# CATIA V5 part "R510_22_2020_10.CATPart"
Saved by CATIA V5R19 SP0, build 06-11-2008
Material "Steel": density 7860 kg/m3, Young's modulus 2e+11 Pa, Poisson ratio 0.266, thermal expansion 1.17e-05 1/K
Bounding box of the stored display mesh (mm): x -9.942 to 9.969, y -9.942 to 9.942, z 0 to 82
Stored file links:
  G:\Podręcznik\CD\Narzędzia\Arkusz Excel\Modele narzędzi\R510.22-2020-10.CATPart
  C:\Program Files\Dassault Systemes\B19\intel_a\startup\materials\Catalog.CATMaterial
  F:\OSTATNIE\DesignTable2.xls
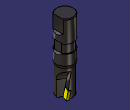
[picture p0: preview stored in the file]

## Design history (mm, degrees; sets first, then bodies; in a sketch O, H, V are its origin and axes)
Parameters
  CuttingType = "CUTTER"
  d = 20 mm {design table}
  D = 20 mm {design table}
  L = 82 mm {design table}
  l = 50 mm {design table}
  alfa = 11 deg {design table}
  gammap = 9 deg {design table}
  S = 3.18 mm {design table}
  epsilon = 85 deg {design table}
  lp = 10 mm {design table}
  x = 0.1131 mm {design table}
  gammaf = -12 deg {design table}
  z = 2 {design table}
  teta = 180 deg {design table}
  `lp'` = 9.8769 mm {design table}
  `lp''` = 5.8466 mm {design table}
Body1 "BODY" (main body), material "Steel"
  Sketch1 "sketch" on yz-plane, origin (0, 0, 0), H (0, 1, 0), V (0, 0, 1)
    line L1 (0, 1.3409) -> (9, 0.2358)
    line L2 (9, 0.2358) -> (9, 32)
    point P3 (9, 32)
    line L3 (9, 32) -> (9, 32)
    point P4 (10, 32)
    line L4 (10, 34.8284) -> (10, 47)
    point P5 (10, 47)
    line L5 (10, 47) -> (9, 47)
    line L6 (9, 47) -> (9, 57)
    line L7 (9, 57) -> (10, 57)
    point P8 (10, 57)
    line L8 (10, 57) -> (10, 81.2929)
    line L9 (10, 81.2929) -> (9.2929, 82)
    line L10 (9.2929, 82) -> (0, 82)
    point P11 (0, 82)
    line L11 (0, 82) -> (0, 1.3409)
    construction line L12 (0, -29.1199) -> (0, 199.3445)
    point P12 (0, -29.1199)
    construction line L13 (0, 0.1131) -> (10, 0.1131)
    point P14 (0, 0.1131)
    point P15 (10, 0.1131)
    construction line L14 (0, 1.3409) -> (10, 0.1131)
    axis line L15 (10, 0.1131) -> (10, -5.5625)
    line L16 (9, 32) -> (10, 34.8284)
    point P17 (9, 32)
    length L6 = 10 {= 0.2*l}
    distance P3 H = 32 {= L-l}
    length L9 = 1
    angle L8 L9 = 45
    distance L6 L8 = 1
    distance L8 L11 = 10 {= d/2}
    length L13 = 10 {= D/2}
    distance H L13 = 0.1131 {= x}
    distance L10 L7 = 25 {= 0.5*l}
    distance P15 L2 = 1
    distance P4 P5 = 15 {= 0.3*l}
    length L16 = 3 {= 0.2*(0.3*l)}
    angle L1 L2 = 83
    vertical: L2 V, L4 V, L6 V, L8 V, L11 V, L12 V, L15 V
    horizontal: L3 H, L5 H, L7 H, L10 H, L13 H
    coincidence: P8 L4, P11 V, P12 V, L1 L14, P14 L12, L3 P4, L4 P4, P3 P17
  Shaft1: profile Sketch1, axis Z axis, angle 360
  Fillet1: radius 1 {= 0.1*D/2}, on edge [face of Shaft1 from Sketch1.L1 | face of Shaft1 from Sketch1.L2]
  Sketch2 on zx-plane, origin (0, 0, 0), H (-1, 0, 0), V (0, 0, 1)
    line L1 (-8, 82) -> (-8, 67)
    line L2 (-8, 67) -> (-10, 65)
    line L3 (-10, 65) -> (-10, 59)
    line L4 (-10, 59) -> (-8, 57)
    point P5 (-8, 57)
    line L5 (-8, 57) -> (-8, 47)
    line L6 (-8, 47) -> (-10, 45)
    point P7 (-10, 45)
    line L7 (-10, 45) -> (-10, 45)
    line L8 (-10, 45) -> (-13, 45)
    line L9 (-13, 45) -> (-13, 82)
    line L10 (-13, 82) -> (-8, 82)
    reference projected line E1 through (0, 0) direction (0, 1) from axis of face of Shaft1 from Sketch1.L8
    reference projected line E2 (-9.2929, 82) -> (9.2929, 82) from edge [face of Shaft1 from Sketch1.L9 | face of Shaft1 from Sketch1.L10]
    distance L3 E1 = 10 {= d/2}
    distance L1 L3 = 2
    angle L2 L3 = 45
    angle L4 L3 = 45
    length L5 = 10 {= l*0.2}
    length L1 = 15 {= 0.3*l}
    distance P5 L10 = 25 {= 0.5*l}
    distance L9 L1 = 5
    distance L7 L5 = 2
    angle L5 L6 = 45
    vertical: L1 V, L3 V, L5 V, L7 V, L9 V
    horizontal: L8 H, L10 H
    coincidence: L10 E2, L1 L5, P7 L8
  Pocket1: profile Sketch2, direction (0, -1, 0), length 8, mirrored extent
  Plane1: type Angle, Angle 150, Direction Z axis, RefPlane yz-plane
  Plane2: type Offset, Offset 1, RefPlane Plane1, reversed
  Sketch3 "gammap_os_obrotu" on Plane2, origin (0.866, -0.5, 0), H (-0.5, -0.866, 0), V (0, 0, 1)
    line L1 (1.3076, 0) -> (-0.9434, 0)
    reference intersected line E1 through (0, 0) direction (-1, 0) from xy-plane
    horizontal: L1 H
    coincidence: E1 L1
  Plane3 "gammap": type Angle, Angle -9 {= -gammap}, Direction Sketch3, RefPlane Plane2
  Plane4: type Offset, Offset 0.5, RefPlane Plane3, reversed
  Sketch4 on Plane4, origin (1.2725, -0.7347, 0.2327), H (-0.5, -0.866, 0), V (-0.1355, 0.0782, 0.9877)
    line L1 (-10, -2.3223) -> (-10, 6.2448)
    distance V L1 = 10 {= D/2}
  Plane5 "gammaf": type Angle, Angle 12 {= -gammaf}, Direction Sketch4, RefPlane Plane4
  Plane6: type Offset, Offset 0.5, RefPlane Plane5
  Plane7: type Angle, Angle 90, Direction Sketch4, RefPlane Plane5
  Sketch5 on Plane7, origin (2.8716, 9.0198, -0.3577), H (0.9503, -0.3114, 0), V (0.0101, 0.0309, 0.9995)
    point P1 (3.6086, 0.3579)
    line L1 (3.6086, 0.3579) -> (0.3714, 0.4819)
    line L2 (0.3714, 0.4819) -> (-0.9703, 9.1423)
    line L3 (-0.9703, 9.1423) -> (2.0776, 10.24)
    line L4 (2.0776, 10.24) -> (3.6086, 0.3579)
    reference projected line E1 (3.9266, -1.6951) -> (2.6151, 6.7709) from Sketch4
    construction line L5 (2.0776, 10.24) -> (-2.825, 9.4805)
    axis line L6 (3.6086, 0.3579) -> (-0.0816, -0.2138)
    reference intersected line E2 through (-0.0001, 0.3579) direction (-1, 0) from xy-plane
    distance L2 L4 = 3.18 {= S}
    length L4 = 10 {= lp}
    angle L5 L3 = 11 {= alfa}
    angle L6 L1 = 11 {= alfa}
    coincidence: L4 E1, P1 E2
    perpendicularity: L5 L2
    parallelism: L6 L5
  Plane8: type Offset, Offset 10 {= D/2}, RefPlane Plane1, reversed
  Sketch6 on Plane8, origin (8.6603, -5, 0), H (-0.5, -0.866, 0), V (0, 0, 1)
    line L1 (-3.5247, -3) -> (-3.5247, 18.3474)
    arc A1 centre (-15.5247, 18.3474) radius 12 from (-3.5247, 18.3474) to (-10, 29) ccw
    point P4 (-10, 29)
    line L2 (-10, 29) -> (-10, -3)
    point P5 (-10, -3)
    line L3 (-10, -3) -> (-3.5247, -3)
    axis line L4 (-10, -3) -> (-3.5247, -2.4335)
    point P6 (-10, -3)
    point P7 (-3.5247, -2.4335)
    reference projected line E1 (-9, 32) -> (9, 32) from edge [face of Shaft1 from Sketch1.L2 | face of Shaft1 from Sketch1.L16]
    distance L2 V = 10 {= D/2}
    angle L4 L2 = 85 {= epsilon}
    distance E1 P4 = 3
    radius A1 = 12
    distance H L3 = 3
    length L4 = 6.5 {= 0.65*lp}
    vertical: L1 V, L2 V
    horizontal: L3 H
    tangency: L1 A1
    coincidence: P6 P5, P7 L1
  Pocket2: profile Sketch6, direction (-0.866, 0.5, 0), up to Plane6
  CircPattern1: of Pocket2, instances 2 {= z}, angular step 180 {= teta}, axis from Z axis
  Sketch7 on Plane5, origin (3.3239, -1.0481, 0.5894), H (-0.3066, -0.9518, 0), V (-0.1456, 0.0469, 0.9882)
    line L1 (-9.7669, 9.3981) -> (-3.8102, 10.1175)
    point P1 (-9.7669, 9.3981)
    reference projected point E1 (-9.7669, 9.3981) from vertex [element of Sketch5 | element of Sketch5]
    reference projected line E2 (-9.4279, -0.899) -> (-9.757, 9.0955) from Sketch5.L4
    length L1 = 6 {= 0.6*lp}
    angle E2 L1 = 85 {= epsilon}
    coincidence: P1 E1
  Slot1: profile Sketch5, centre curve Sketch7
  CircPattern2: of Slot1, instances 2 {= z}, angular step 180 {= teta}, axis from Z axis
Body2 "INSERTS"
  Sketch8 "CUT" on yz-plane, origin (0, 0, 0), H (0, 1, 0), V (0, 0, 1)
    line L1 (4.1757, 0.5096) -> (10, 0)
    point P2 (10, 0)
    line L2 (10, 0) -> (10, 9.8769)
    line L3 (10, 9.8769) -> (4.1757, 10.3864)
    line L4 (4.1757, 10.3864) -> (4.1757, 0.5096)
    angle L3 L4 = 85
    length L2 = 9.8769 {= `lp'`}
    length L1 = 5.8466 {= `lp''`}
    distance L2 V = 10 {= D/2}
    vertical: L2 V, L4 V
    parallelism: L3 L1
    coincidence: P2 H
  Sketch9 "NOCUT" on yz-plane, origin (0, 0, 0), H (0, 1, 0), V (0, 0, 1)
    axis line L1 (10, 0) -> (0, 0.8749)
    point P1 (0, 0.8749)
    point P2 (10, 0)
    reference projected line E1 (4.0228, 0.5229) -> (10, 0) from Sketch8.L1
    reference projected point E2 (10, 0) from vertex [element of Sketch8 | element of Sketch8]
    line L2 (0, 0.8749) -> (4.1757, 0.5096)
    point P3 (4.1757, 0.5096)
    line L3 (4.1757, 0.5096) -> (4.1757, 10.3864)
    line L4 (4.1757, 10.3864) -> (9, 9.9644)
    line L5 (9, 9.9644) -> (9, 32)
    line L6 (9, 32) -> (10, 32)
    line L7 (10, 32) -> (10, 47)
    line L8 (10, 47) -> (9, 47)
    line L9 (9, 47) -> (9, 57)
    line L10 (9, 57) -> (10, 57)
    point P11 (10, 57)
    line L11 (10, 57) -> (10, 81.2929)
    point P12 (10, 82)
    line L12 (9.2929, 82) -> (0, 82)
    point P13 (0, 82)
    line L13 (0, 82) -> (0, 0.8749)
    line L14 (10, 81.2929) -> (9.2929, 82)
    length L9 = 10 {= 0.2*l}
    length L7 = 15 {= 0.3*l}
    distance L6 H = 32 {= L-l}
    distance L11 L13 = 10 {= d/2}
    distance L9 L11 = 1
    distance P3 P2 = 5.8466 {= `lp''`}
    distance L9 L7 = 1
    distance L5 P2 = 1
    length L3 = 9.8769 {= `lp'`}
    angle L10 L9 = 90
    distance P11 P12 = 25 {= 0.5*l}
    angle L11 L14 = 45
    length L14 = 1
    coincidence: P1 V, L1 E1, P2 E2, P13 V, L11 P12, L12 P12
    parallelism: L2 L1, L4 L1
    vertical: L3 V, L5 V, L7 V, L9 V, L11 V, L13 V
    horizontal: L6 H, L8 H, L12 H
  Sketch10 on Plane7, origin (2.8716, 9.0198, -0.3577), H (0.9503, -0.3114, 0), V (0.0101, 0.0309, 0.9995)
    point P1 (3.6086, 0.3579)
    line L1 (3.6086, 0.3579) -> (0.3714, 0.4819)
    line L2 (0.3714, 0.4819) -> (-0.9703, 9.1423)
    line L3 (-0.9703, 9.1423) -> (2.0776, 10.24)
    line L4 (2.0776, 10.24) -> (3.6086, 0.3579)
    reference intersected line E1 through (3.5711, 0.5998) direction (0.1531, -0.9882) from Plane5
    reference intersected line E2 through (-0.0001, 0.3579) direction (-1, 0) from xy-plane
    construction line L5 (2.0776, 10.24) -> (-8.7731, 8.559)
    axis line L6 (3.6086, 0.3579) -> (-3.0022, -0.6663)
    distance L2 L4 = 3.18 {= S}
    length L4 = 10 {= lp}
    angle L3 L5 = 11 {= alfa}
    angle L6 L1 = 11 {= alfa}
    coincidence: L4 E1, E2 P1
    perpendicularity: L5 L2
    parallelism: L6 L5
  Sketch11 on Plane5, origin (3.3239, -1.0481, 0.5894), H (-0.3066, -0.9518, 0), V (-0.1456, 0.0469, 0.9882)
    line L1 (-9.7669, 9.3981) -> (-3.8102, 10.1175)
    point P1 (-9.7669, 9.3981)
    reference projected point E1 (-9.7669, 9.3981) from vertex [element of Sketch10 | element of Sketch10]
    reference projected line E2 (-9.4381, -0.5873) -> (-9.7673, 9.4073) from Sketch10.L4
    angle L1 E2 = 85 {= epsilon}
    length L1 = 6 {= 0.6*lp}
    coincidence: P1 E1
  Rib1: profile Sketch10, centre curve Sketch11
  CircPattern3: of the body so far, instances 2 {= z}, angular step 180 {= teta}, axis from Z axis
  Sketch12 on face of Rib1, origin (0.0796, 0.1331, 1.2424), H (0.8083, -0.5887, 0), V (-0.5842, -0.8021, 0.1239)
    point P1 (0.4549, -10.026)
    line L1 (0.4549, -10.026) -> (-2.4414, -8.4217)
    line L2 (-2.4414, -8.4217) -> (-2.6264, -9.0259)
    point P3 (-2.6264, -9.0259)
    line L3 (-2.6264, -9.0259) -> (0.4549, -10.026)
    reference projected point E1 (0.4549, -10.026) from vertex [face of Rib1 | face of Rib1 | face of Rib1]
    reference projected line E2 (-2.6666, -9.0128) -> (0.4147, -10.0129) from edge [face of Rib1 | face of Rib1]
    reference projected point E3 (-2.6264, -9.0259) from vertex [face of Rib1 | face of Rib1 | face of Rib1]
    reference projected line E4 (-2.629, -9.0344) -> (-0.8719, -3.2974) from edge [face of Rib1 | face of Rib1]
    angle L1 L3 = 11
    coincidence: E1 P1, L3 E2, P3 E3, L2 E4
  Pocket3: profile Sketch12, direction along edge [face of Rib1 | face of Rib1], length 10 {= lp}
  CircPattern4: of Pocket3, instances 2 {= z}, angular step 180 {= teta}, axis from Z axis
Relations
  design table, configuration 2, drives d, D, L, l, alfa, gammap, S, epsilon, lp, x, gammaf, z, teta, `lp'`, `lp''`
